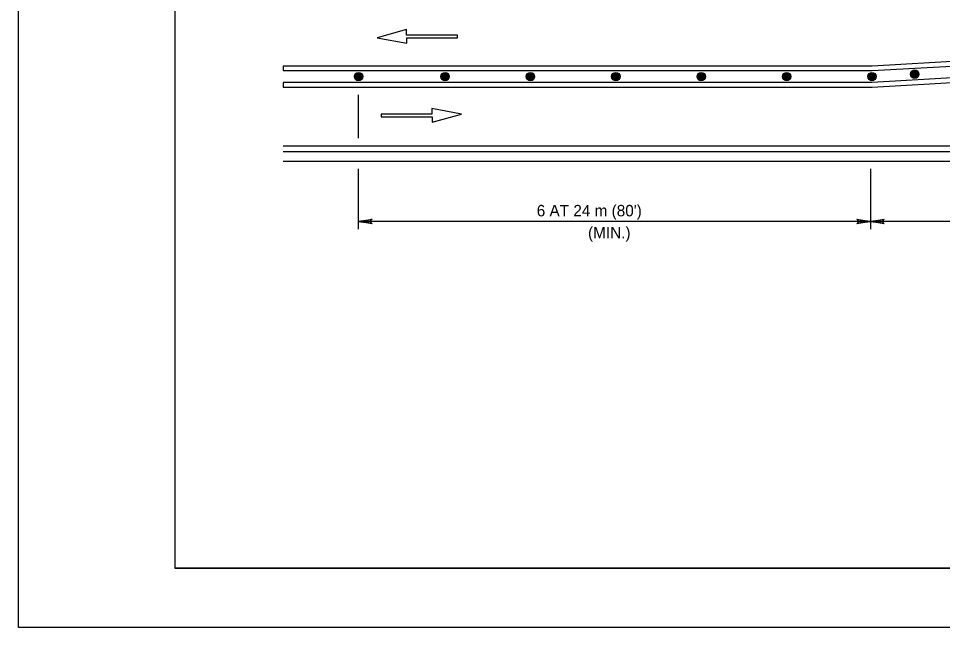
# Model space of a CAD drawing. Extents: x 639362 to 641108, y 298458 to 299646.
# Drawn here: x 639362.3 to 639604.4, y 298457.6 to 298617.3 of the extents above; entities that cross this region are included whole.
import ezdxf

# ---------------------------------------------------------------- set-up
doc = ezdxf.new("R2010")
doc.units = 0
for name, color, linetype in [('1', 7, 'Continuous'), ('2', 7, 'Continuous'), ('3', 7, 'Continuous'), ('PLT-BNDY', 7, 'Continuous')]:
    doc.layers.add(name, color=color, linetype=linetype)

# ---------------------------------------------------------------- blocks, each defined once
blk = doc.blocks.new('RARROW')
at = {"layer": '3'}
blk.add_lwpolyline([(-2.2695, 0.285), (-2.184875, 0.12075), (0, 0), (-2.2695, 0.285), (-2.38575, 0.384625), (0, 0), (-2.183125, -0.108), (-2.262875, -0.2705), (0, 0), (-2.38575, -0.379125), (-2.262875, -0.2705)], dxfattribs=at)

msp = doc.modelspace()

# ---------------------------------------------------------------- linework, layer by layer
at = {"layer": '1'}
for p, q in [((639403.27, 299037.19), (639403.27, 298473.19)), ((640189.27, 298473.19), (639403.27, 298473.19)), ((639403.27, 298473.19), (639989.27, 298473.19))]:
    msp.add_line(p, q, dxfattribs=at)
at = {"layer": '2'}
for p, q in [((639797.98, 298616.83), (639585.9, 298604.78)), ((639585.93, 298603.58), (639798.02, 298615.63)), ((639463.99, 298614.33), (639456.27, 298612.21)), ((639463.99, 298612.88), (639463.99, 298614.33)), ((639456.27, 298612.21), (639464.07, 298610.74)), ((639477.32, 298612.88), (639463.99, 298612.88)), ((639464.07, 298610.74), (639464.07, 298612.18)), ((639464.07, 298612.18), (639477.32, 298612.18)), ((639477.32, 298612.18), (639477.32, 298612.88)), ((639797.98, 298612.52), (639585.9, 298600.47)), ((639585.93, 298599.27), (639798.02, 298611.32)), ((639585.9, 298604.78), (639431.63, 298604.78)), ((639431.63, 298604.78), (639431.63, 298603.58)), ((639431.63, 298603.58), (639585.93, 298603.58)), ((639585.9, 298600.47), (639431.63, 298600.47)), ((639431.63, 298600.47), (639431.63, 298599.27)), ((639431.63, 298599.27), (639585.93, 298599.27)), ((639451.32, 298597.27), (639451.32, 298585.85)), ((639470.58, 298592.19), (639457.33, 298592.19)), ((639457.33, 298592.19), (639457.33, 298591.48)), ((639457.33, 298591.48), (639470.66, 298591.48)), ((639478.38, 298592.16), (639470.58, 298593.63)), ((639470.58, 298593.63), (639470.58, 298592.19)), ((639470.66, 298590.04), (639478.38, 298592.16)), ((639470.66, 298591.48), (639470.66, 298590.04)), ((639431.63, 298583.85), (639951.12, 298583.85)), ((639431.63, 298582.35), (639951.12, 298582.35)), ((639431.63, 298579.85), (639951.12, 298579.85)), ((639451.32, 298577.85), (639451.32, 298562.02)), ((639585.52, 298577.85), (639585.52, 298562.02)), ((639585.52, 298564.02), (639451.32, 298564.02)), ((639798, 298564.02), (639585.52, 298564.02))]:
    msp.add_line(p, q, dxfattribs=at)
for centre, radius in [((639597.08, 298602.66), 1.1), ((639597.08, 298602.66), 1.02), ((639597.08, 298602.66), 0.946), ((639597.08, 298602.66), 0.868), ((639597.08, 298602.66), 0.789), ((639451.4, 298602.03), 1.1), ((639451.4, 298602.03), 1.02), ((639451.4, 298602.03), 0.946), ((639451.4, 298602.03), 0.868), ((639451.4, 298602.03), 0.789), ((639451.4, 298602.03), 0.711), ((639451.4, 298602.03), 0.633), ((639451.4, 298602.03), 0.554), ((639451.4, 298602.03), 0.476), ((639451.4, 298602.03), 0.398), ((639451.4, 298602.03), 0.32), ((639451.4, 298602.03), 0.241), ((639451.4, 298602.03), 0.163), ((639451.4, 298602.03), 0.0846), ((639474.05, 298602.03), 1.1), ((639474.05, 298602.03), 1.02), ((639474.05, 298602.03), 0.946), ((639474.05, 298602.03), 0.868), ((639474.05, 298602.03), 0.789), ((639474.05, 298602.03), 0.711), ((639474.05, 298602.03), 0.633), ((639474.05, 298602.03), 0.554), ((639474.05, 298602.03), 0.476), ((639474.05, 298602.03), 0.398), ((639474.05, 298602.03), 0.32), ((639474.05, 298602.03), 0.241), ((639474.05, 298602.03), 0.163), ((639474.05, 298602.03), 0.0846), ((639496.42, 298602.03), 1.1), ((639496.42, 298602.03), 1.02), ((639496.42, 298602.03), 0.946), ((639496.42, 298602.03), 0.868), ((639496.42, 298602.03), 0.789), ((639496.42, 298602.03), 0.711), ((639496.42, 298602.03), 0.633), ((639496.42, 298602.03), 0.554), ((639496.42, 298602.03), 0.476), ((639496.42, 298602.03), 0.398), ((639496.42, 298602.03), 0.32), ((639496.42, 298602.03), 0.241), ((639496.42, 298602.03), 0.163), ((639496.42, 298602.03), 0.0846), ((639518.79, 298602.03), 1.1), ((639518.79, 298602.03), 1.02), ((639518.79, 298602.03), 0.946), ((639518.79, 298602.03), 0.868), ((639518.79, 298602.03), 0.789), ((639518.79, 298602.03), 0.711), ((639518.79, 298602.03), 0.633), ((639518.79, 298602.03), 0.554), ((639518.79, 298602.03), 0.476), ((639518.79, 298602.03), 0.398), ((639518.79, 298602.03), 0.32), ((639518.79, 298602.03), 0.241), ((639518.79, 298602.03), 0.163), ((639518.79, 298602.03), 0.0846), ((639541.16, 298602.03), 1.1), ((639541.16, 298602.03), 1.02), ((639541.16, 298602.03), 0.946), ((639541.16, 298602.03), 0.868), ((639541.16, 298602.03), 0.789), ((639541.16, 298602.03), 0.711), ((639541.16, 298602.03), 0.633), ((639541.16, 298602.03), 0.554), ((639541.16, 298602.03), 0.476), ((639541.16, 298602.03), 0.398), ((639541.16, 298602.03), 0.32), ((639541.16, 298602.03), 0.241), ((639541.16, 298602.03), 0.163), ((639541.16, 298602.03), 0.0846), ((639563.54, 298602.03), 1.1), ((639563.54, 298602.03), 1.02), ((639563.54, 298602.03), 0.946), ((639563.54, 298602.03), 0.868), ((639563.54, 298602.03), 0.789), ((639563.54, 298602.03), 0.711), ((639563.54, 298602.03), 0.633), ((639563.54, 298602.03), 0.554), ((639563.54, 298602.03), 0.476), ((639563.54, 298602.03), 0.398), ((639563.54, 298602.03), 0.32), ((639563.54, 298602.03), 0.241), ((639563.54, 298602.03), 0.163), ((639563.54, 298602.03), 0.0846), ((639585.89, 298602.03), 1.1), ((639585.89, 298602.03), 1.02), ((639585.89, 298602.03), 0.946), ((639585.89, 298602.03), 0.868), ((639585.89, 298602.03), 0.789), ((639585.89, 298602.03), 0.711), ((639585.89, 298602.03), 0.633), ((639585.89, 298602.03), 0.554), ((639585.89, 298602.03), 0.476), ((639585.89, 298602.03), 0.398), ((639585.89, 298602.03), 0.32), ((639585.89, 298602.03), 0.241), ((639585.89, 298602.03), 0.163), ((639585.89, 298602.03), 0.0846), ((639597.08, 298602.66), 0.711), ((639597.08, 298602.66), 0.633), ((639597.08, 298602.66), 0.554), ((639597.08, 298602.66), 0.476), ((639597.08, 298602.66), 0.398), ((639597.08, 298602.66), 0.32), ((639597.08, 298602.66), 0.241), ((639597.08, 298602.66), 0.163), ((639597.08, 298602.66), 0.0846)]:
    msp.add_circle(centre, radius, dxfattribs=at)
at = {"layer": 'PLT-BNDY'}
msp.add_lwpolyline([(639362.31, 299051.63), (640203.31, 299051.63), (640203.31, 298457.63), (639362.31, 298457.63)], close=True, dxfattribs=at)

# ---------------------------------------------------------------- block references
at = {"layer": '2', "xscale": 1.5089217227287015, "yscale": 1.5711553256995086, "rotation": 180}
for p in [(639451.32, 298564.02), (639585.52, 298564.02)]:
    msp.add_blockref('RARROW', p, dxfattribs=at)
at = {"layer": '2', "xscale": 1.5089217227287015, "yscale": 1.5711553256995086}
msp.add_blockref('RARROW', (639585.52, 298564.02), dxfattribs=at)

# ---------------------------------------------------------------- texts
at = {"layer": '2'}
for s, p in [("6 AT 24 m (80')", (639498.07, 298565.39)), ('(MIN.)', (639511.51, 298559.63))]:
    msp.add_text(s, height=3, dxfattribs=at).set_placement(p)

doc.saveas('drawing.dxf')
